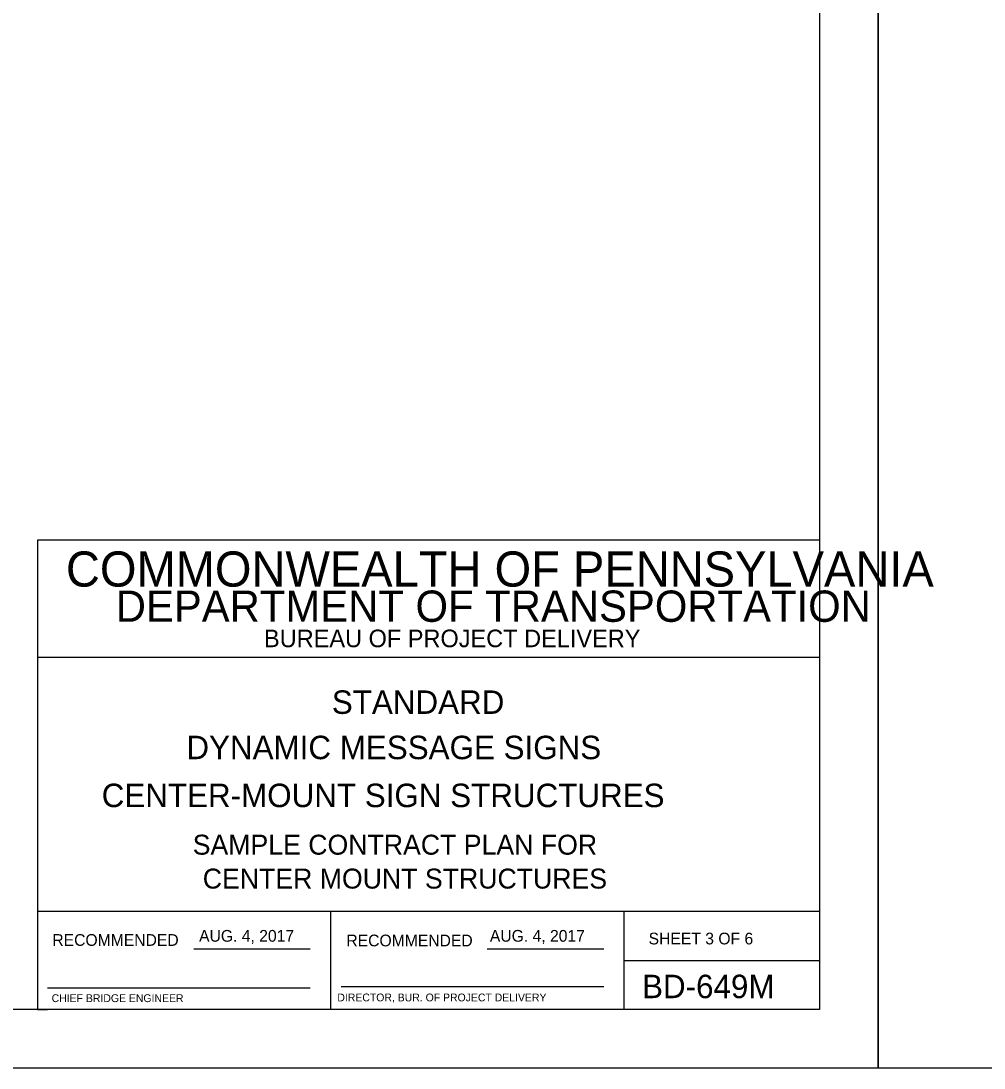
# Model space of a CAD drawing. Extents: x 3829340 to 3831660, y 499389 to 501171.
# Drawn here: x 3829961.7 to 3830208.1, y 499389.2 to 499657 of the extents above; entities that cross this region are included whole.
import ezdxf

# ---------------------------------------------------------------- set-up
doc = ezdxf.new("R2010")
doc.units = 0
for name, color, linetype in [('10', 7, 'Continuous'), ('2', 7, 'Continuous'), ('PLT-BNDY', 7, 'Continuous')]:
    doc.layers.add(name, color=color, linetype=linetype)

msp = doc.modelspace()

# ---------------------------------------------------------------- linework, layer by layer
at = {"layer": '2'}
for p, q in [((3830165.96, 499968.19), (3830165.96, 499404.19)), ((3830165.96, 499524.19), (3829965.96, 499524.19)), ((3829965.96, 499524.19), (3829965.96, 499404.19)), ((3830165.96, 499494.19), (3829965.96, 499494.19)), ((3830165.96, 499429.19), (3829965.96, 499429.19)), ((3830040.96, 499404.19), (3830040.96, 499429.19)), ((3830115.96, 499429.19), (3830115.96, 499404.19)), ((3830005.93, 499419.69), (3830035.69, 499419.69)), ((3830080.93, 499419.69), (3830110.83, 499419.69)), ((3830115.96, 499416.69), (3830165.96, 499416.69)), ((3829968.46, 499409.69), (3830035.69, 499409.69)), ((3830043.59, 499410.06), (3830110.83, 499410.06)), ((3830165.96, 499404.19), (3829379.96, 499404.19)), ((3829965.96, 499404.19), (3829968.53, 499404.19))]:
    msp.add_line(p, q, dxfattribs=at)
at = {"layer": 'PLT-BNDY'}
for points in [[(3829339.96, 499983.19), (3830180.96, 499983.19), (3830180.96, 499389.19), (3829339.96, 499389.19)], [(3830180.96, 499983.19), (3831021.96, 499983.19), (3831021.96, 499389.19), (3830180.96, 499389.19)]]:
    msp.add_lwpolyline(points, close=True, dxfattribs=at)

# ---------------------------------------------------------------- texts
at = {"layer": '10'}
for s, height, p in [('STANDARD ', 6, (3830041.23, 499479.77)), ('DYNAMIC MESSAGE SIGNS', 6, (3830004.03, 499468.18)), ('CENTER-MOUNT SIGN STRUCTURES', 6, (3829982.36, 499455.92)), ('SAMPLE CONTRACT PLAN FOR', 5.1, (3830005.64, 499443.76)), ('CENTER MOUNT STRUCTURES', 5.1, (3830008.21, 499435.09))]:
    msp.add_text(s, height=height, dxfattribs=at).set_placement(p)
at = {"layer": '2'}
for s, height, p in [('COMMONWEALTH OF PENNSYLVANIA', 9, (3829973.21, 499512.31)), ('DEPARTMENT OF TRANSPORTATION', 8.0002, (3829985.96, 499503.31)), ('BUREAU OF PROJECT DELIVERY', 4.5, (3830023.88, 499496.82)), ('RECOMMENDED', 3, (3829969.73, 499420.44)), ('RECOMMENDED', 3, (3830044.95, 499420.31))]:
    msp.add_text(s, height=height, rotation=360, dxfattribs=at).set_placement(p)
for s, height, p in [('AUG. 4, 2017', 3, (3830007.27, 499421.5)), ('AUG. 4, 2017', 3, (3830081.66, 499421.5)), ('SHEET 3 OF 6', 3, (3830122.27, 499420.81)), ('BD-649M', 6, (3830120.59, 499407.06)), ('CHIEF BRIDGE ENGINEER', 2.0002, (3829969.55, 499406.06)), ('  DIRECTOR, BUR. OF PROJECT DELIVERY', 2.0002, (3830041.15, 499406.24))]:
    msp.add_text(s, height=height, dxfattribs=at).set_placement(p)

doc.saveas('drawing.dxf')
